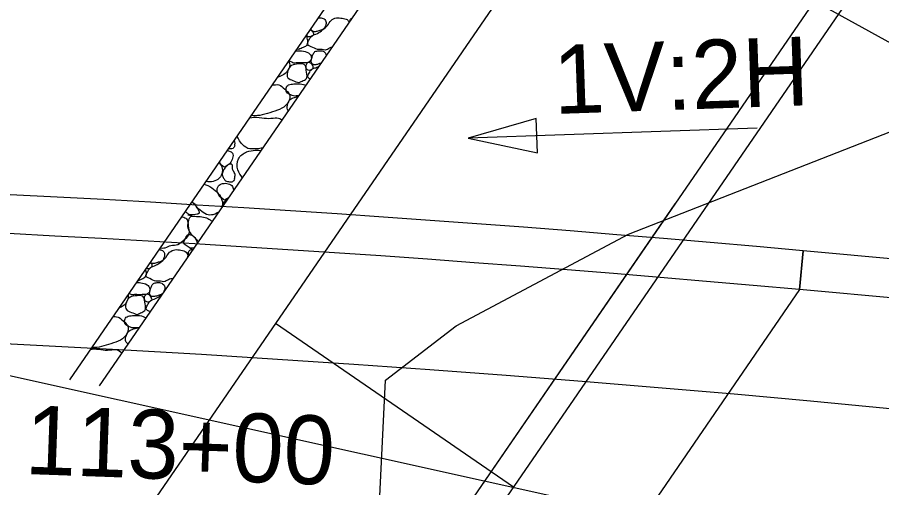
# Model space of a CAD drawing. Extents: x 1385284 to 1385995, y 1975154 to 1975620.
# Drawn here: x 1385550.34 to 1385581.75, y 1975494.43 to 1975511.52 of the extents above; entities that cross this region are included whole.
import ezdxf

# ---------------------------------------------------------------- set-up
doc = ezdxf.new("R2010")
doc.units = 0
for name, color, linetype in [('B-Super-Deck', 7, 'Continuous'), ('Default', 7, 'Continuous'), ('DTM_CONTOURS_MINOR', 7, 'Continuous'), ('R_Bridge', 7, 'Continuous'), ('R_Horz Alg Annot', 7, 'Continuous'), ('R_Proposed Const Limits', 7, 'Continuous'), ('R_Proposed Road', 7, 'Continuous')]:
    doc.layers.add(name, color=color, linetype=linetype)

msp = doc.modelspace()

# ---------------------------------------------------------------- linework, layer by layer
at = {"layer": 'B-Super-Deck'}
for p, q in [((1385588.853, 1975502.134), (1385578.894, 1975503.042)), ((1385588.724, 1975500.723), (1385578.766, 1975501.631))]:
    msp.add_line(p, q, dxfattribs=at)
at = {"layer": 'Default'}
for p, q in [((1385552.239, 1975498.351), (1385589.716, 1975552.857)), ((1385590.54, 1975552.29), (1385553.307, 1975498.139)), ((1385601.664, 1975544.642), (1385558.992, 1975482.58)), ((1385559.816, 1975482.013), (1385602.488, 1975544.075)), ((1385577.219, 1975507.501), (1385566.72, 1975507.137)), ((1385574.233, 1975504.747), (1385558.972, 1975482.551)), ((1385578.766, 1975501.631), (1385578.894, 1975503.042)), ((1385568.368, 1975494.451), (1385559.716, 1975500.4))]:
    msp.add_line(p, q, dxfattribs=at)
msp.add_lwpolyline([(1385569.196, 1975507.848), (1385566.72, 1975507.137), (1385569.24, 1975506.599)], close=True, dxfattribs=at)
for points in [[(1385561.294, 1975510.355), (1385561.222, 1975510.35), (1385561.087, 1975510.43), (1385560.827, 1975510.519), (1385560.941, 1975510.688), (1385561.02, 1975510.875), (1385561.245, 1975510.919), (1385561.445, 1975511.078), (1385561.625, 1975511.22), (1385561.72, 1975511.426), (1385561.931, 1975511.519), (1385562.146, 1975511.493), (1385562.342, 1975511.455), (1385562.378, 1975511.375), (1385562.386, 1975511.344)], [(1385561.285, 1975511.508), (1385561.348, 1975511.511), (1385561.468, 1975511.502), (1385561.574, 1975511.382), (1385561.55, 1975511.222), (1385561.49, 1975511.105), (1385561.437, 1975511.075)], [(1385562.426, 1975511.402), (1385562.436, 1975511.44), (1385562.453, 1975511.474), (1385562.49, 1975511.495)], [(1385560.985, 1975511.071), (1385561.004, 1975511.063), (1385561.064, 1975511.02), (1385561.131, 1975510.898), (1385561.043, 1975510.838), (1385561.009, 1975510.809)], [(1385561.437, 1975511.075), (1385561.389, 1975511.06), (1385561.293, 1975511.037), (1385561.159, 1975510.983), (1385561.037, 1975511.023), (1385561.005, 1975511.078), (1385561.005, 1975511.1)], [(1385560.841, 1975510.862), (1385560.847, 1975510.837), (1385560.866, 1975510.733), (1385560.906, 1975510.505), (1385560.722, 1975510.427), (1385560.619, 1975510.379), (1385560.57, 1975510.355)], [(1385561.009, 1975510.809), (1385560.972, 1975510.809), (1385560.903, 1975510.807), (1385560.858, 1975510.848), (1385560.844, 1975510.866)], [(1385560.461, 1975510.309), (1385560.545, 1975510.311), (1385560.738, 1975510.315), (1385560.988, 1975510.216), (1385561.047, 1975510.03), (1385560.951, 1975509.864), (1385560.745, 1975509.871), (1385560.585, 1975509.866), (1385560.465, 1975509.872)], [(1385560.57, 1975510.355), (1385560.548, 1975510.358), (1385560.525, 1975510.363), (1385560.503, 1975510.37)], [(1385561.359, 1975509.851), (1385561.338, 1975509.845), (1385561.267, 1975509.828), (1385561.159, 1975509.78), (1385561.032, 1975509.822), (1385561.005, 1975509.928), (1385561.035, 1975510.042), (1385561.078, 1975510.169), (1385561.139, 1975510.294), (1385561.29, 1975510.31), (1385561.461, 1975510.306), (1385561.542, 1975510.213), (1385561.559, 1975510.162), (1385561.562, 1975510.145)], [(1385561.762, 1975510.436), (1385561.749, 1975510.433), (1385561.676, 1975510.414), (1385561.539, 1975510.296), (1385561.373, 1975510.375), (1385561.294, 1975510.355)], [(1385560.465, 1975509.872), (1385560.41, 1975509.848), (1385560.31, 1975509.888), (1385560.233, 1975509.931), (1385560.211, 1975509.946)], [(1385560.199, 1975509.928), (1385560.203, 1975509.92), (1385560.267, 1975509.811), (1385560.172, 1975509.557), (1385559.973, 1975509.407), (1385559.85, 1975509.36), (1385559.795, 1975509.341)], [(1385560.57, 1975509.152), (1385560.499, 1975509.162), (1385560.354, 1975509.231), (1385560.131, 1975509.302), (1385560.134, 1975509.53), (1385560.244, 1975509.776), (1385560.46, 1975509.825), (1385560.821, 1975509.855), (1385560.824, 1975509.613), (1385560.906, 1975509.302), (1385560.722, 1975509.224), (1385560.619, 1975509.176), (1385560.57, 1975509.152)], [(1385561.009, 1975509.606), (1385560.972, 1975509.606), (1385560.887, 1975509.604), (1385560.808, 1975509.685), (1385560.816, 1975509.803), (1385560.9, 1975509.906), (1385561.027, 1975509.855), (1385561.131, 1975509.695), (1385561.043, 1975509.635), (1385561.009, 1975509.606)], [(1385560.97, 1975509.284), (1385560.936, 1975509.306), (1385560.856, 1975509.357), (1385560.941, 1975509.485), (1385561.02, 1975509.672), (1385561.196, 1975509.679), (1385561.28, 1975509.744), (1385561.292, 1975509.752)], [(1385559.606, 1975509.066), (1385559.675, 1975509.067), (1385559.852, 1975509.112), (1385560.045, 1975508.919), (1385560.298, 1975508.715), (1385560.172, 1975508.354), (1385559.883, 1975508.164), (1385559.515, 1975508.064), (1385559.144, 1975507.935), (1385558.912, 1975507.95), (1385558.841, 1975507.953)], [(1385560.465, 1975508.669), (1385560.41, 1975508.645), (1385560.265, 1975508.703), (1385560.104, 1975508.789), (1385560.093, 1975508.956), (1385560.17, 1975509.087), (1385560.389, 1975509.106), (1385560.617, 1975509.123), (1385560.785, 1975509.078), (1385560.818, 1975509.064)], [(1385560.176, 1975508.13), (1385560.129, 1975508.181), (1385560.134, 1975508.328), (1385560.244, 1975508.573), (1385560.408, 1975508.611), (1385560.512, 1975508.645), (1385560.535, 1975508.652)], [(1385560.545, 1975508.666), (1385560.518, 1975508.667), (1385560.492, 1975508.668), (1385560.465, 1975508.669)], [(1385558.788, 1975507.876), (1385558.877, 1975507.894), (1385559.135, 1975507.899), (1385559.475, 1975507.828), (1385559.795, 1975507.902), (1385559.906, 1975507.829), (1385559.946, 1975507.795)], [(1385558.838, 1975506.75), (1385558.77, 1975506.716), (1385558.547, 1975506.853), (1385558.41, 1975507.022), (1385558.34, 1975507.17), (1385558.327, 1975507.205)], [(1385558.237, 1975506.851), (1385558.227, 1975506.826), (1385558.179, 1975506.736), (1385558.09, 1975506.747), (1385558.027, 1975506.746), (1385558.011, 1975506.746)], [(1385558.217, 1975507.045), (1385558.224, 1975507.017), (1385558.267, 1975506.96), (1385558.219, 1975506.881), (1385558.237, 1975506.851)], [(1385557.972, 1975506.689), (1385557.987, 1975506.686), (1385558.067, 1975506.661), (1385558.205, 1975506.578), (1385558.154, 1975506.34), (1385558.041, 1975506.175), (1385557.937, 1975506.127), (1385557.911, 1975506.117)], [(1385558.513, 1975505.71), (1385558.457, 1975505.769), (1385558.32, 1975505.943), (1385558.303, 1975506.413), (1385558.68, 1975506.669), (1385558.99, 1975506.699), (1385559.141, 1975506.69), (1385559.184, 1975506.687)], [(1385559.244, 1975506.774), (1385559.182, 1975506.76), (1385559.047, 1975506.738), (1385558.91, 1975506.747), (1385558.838, 1975506.75)], [(1385557.677, 1975506.26), (1385557.728, 1975506.18), (1385557.81, 1975506.043), (1385557.772, 1975505.759), (1385557.587, 1975505.586), (1385557.418, 1975505.542), (1385557.334, 1975505.543)], [(1385557.911, 1975506.117), (1385557.88, 1975506.043), (1385557.74, 1975506.164), (1385557.679, 1975506.244), (1385557.673, 1975506.254)], [(1385558.237, 1975505.648), (1385558.227, 1975505.623), (1385558.179, 1975505.533), (1385558.056, 1975505.548), (1385557.878, 1975505.567), (1385557.84, 1975505.683), (1385557.766, 1975505.792), (1385557.805, 1975505.956), (1385557.899, 1975506.068), (1385557.976, 1975506.156), (1385558.056, 1975506.212), (1385558.181, 1975506.161), (1385558.138, 1975506.044), (1385558.2, 1975505.918), (1385558.282, 1975505.782), (1385558.219, 1975505.678), (1385558.237, 1975505.648)], [(1385557.334, 1975505.543), (1385557.29, 1975505.541), (1385557.246, 1975505.552), (1385557.203, 1975505.57)], [(1385557.125, 1975505.457), (1385557.213, 1975505.438), (1385557.407, 1975505.342), (1385557.662, 1975505.132), (1385557.79, 1975504.89), (1385557.804, 1975504.713), (1385557.795, 1975504.666)], [(1385557.911, 1975504.914), (1385557.88, 1975504.84), (1385557.675, 1975505.021), (1385557.573, 1975505.2), (1385557.624, 1975505.42), (1385557.788, 1975505.493), (1385558.015, 1975505.5), (1385558.176, 1975505.387), (1385558.193, 1975505.276), (1385558.187, 1975505.237)], [(1385557.779, 1975504.643), (1385557.778, 1975504.674), (1385557.815, 1975504.766), (1385557.899, 1975504.865), (1385557.958, 1975504.934), (1385557.993, 1975504.96), (1385557.999, 1975504.963)], [(1385558, 1975504.965), (1385557.994, 1975504.96), (1385557.965, 1975504.937), (1385557.937, 1975504.924), (1385557.911, 1975504.914)], [(1385556.688, 1975504.821), (1385556.726, 1975504.797), (1385556.807, 1975504.711), (1385556.87, 1975504.58), (1385557.057, 1975504.331), (1385556.307, 1975504.348), (1385556.693, 1975504.338), (1385556.685, 1975504.34)], [(1385557.334, 1975504.34), (1385557.262, 1975504.337), (1385557.08, 1975504.421), (1385556.887, 1975504.6), (1385556.759, 1975504.744), (1385556.694, 1975504.83)], [(1385556.315, 1975504.279), (1385556.318, 1975504.278), (1385556.373, 1975504.269), (1385556.54, 1975504.189), (1385556.532, 1975503.961), (1385556.619, 1975503.65), (1385556.404, 1975503.443), (1385556.182, 1975503.221), (1385555.906, 1975503.253), (1385555.698, 1975503.111), (1385555.58, 1975503.132), (1385555.53, 1975503.138)], [(1385556.651, 1975504.34), (1385556.604, 1975504.339), (1385556.53, 1975504.394), (1385556.46, 1975504.444), (1385556.44, 1975504.462)], [(1385556.91, 1975503.38), (1385556.908, 1975503.383), (1385556.826, 1975503.466), (1385556.673, 1975503.624), (1385556.514, 1975503.864), (1385556.546, 1975504.09), (1385556.617, 1975504.332), (1385556.846, 1975504.28), (1385557.116, 1975504.285), (1385557.309, 1975504.186), (1385557.402, 1975504.126), (1385557.417, 1975504.116)], [(1385557.645, 1975504.448), (1385557.627, 1975504.435), (1385557.525, 1975504.367), (1385557.418, 1975504.339), (1385557.334, 1975504.34)], [(1385556.651, 1975503.137), (1385556.604, 1975503.136), (1385556.508, 1975503.209), (1385556.345, 1975503.302), (1385556.454, 1975503.487), (1385556.502, 1975503.652), (1385556.683, 1975503.626), (1385556.802, 1975503.521), (1385556.846, 1975503.404), (1385556.871, 1975503.335), (1385556.874, 1975503.327)], [(1385555.425, 1975501.934), (1385555.353, 1975501.929), (1385555.218, 1975502.009), (1385554.958, 1975502.099), (1385555.072, 1975502.267), (1385555.151, 1975502.454), (1385555.376, 1975502.499), (1385555.576, 1975502.657), (1385555.755, 1975502.799), (1385555.85, 1975503.005), (1385556.062, 1975503.098), (1385556.277, 1975503.072), (1385556.512, 1975503.006), (1385556.526, 1975502.894), (1385556.533, 1975502.831)], [(1385555.494, 1975503.085), (1385555.531, 1975503.081), (1385555.615, 1975503.062), (1385555.705, 1975502.961), (1385555.681, 1975502.801), (1385555.62, 1975502.684), (1385555.567, 1975502.654)], [(1385556.533, 1975502.831), (1385556.534, 1975502.856), (1385556.551, 1975502.938), (1385556.589, 1975503.086), (1385556.681, 1975503.093), (1385556.712, 1975503.091)], [(1385556.749, 1975503.145), (1385556.7, 1975503.141), (1385556.514, 1975503.14), (1385556.693, 1975503.135), (1385556.685, 1975503.137)], [(1385555.14, 1975502.388), (1385555.102, 1975502.388), (1385555.064, 1975502.387), (1385555.026, 1975502.403), (1385555.025, 1975502.404)], [(1385555.171, 1975502.616), (1385555.218, 1975502.575), (1385555.261, 1975502.477), (1385555.173, 1975502.417), (1385555.14, 1975502.388)], [(1385555.567, 1975502.654), (1385555.52, 1975502.639), (1385555.424, 1975502.616), (1385555.29, 1975502.563), (1385555.206, 1975502.585), (1385555.171, 1975502.616)], [(1385554.993, 1975502.356), (1385555.017, 1975502.27), (1385555.034, 1975502.083), (1385554.853, 1975502.007), (1385554.751, 1975501.959), (1385554.703, 1975501.935)], [(1385554.671, 1975501.889), (1385554.729, 1975501.888), (1385554.891, 1975501.884), (1385555.118, 1975501.795), (1385555.178, 1975501.609), (1385555.082, 1975501.443), (1385554.876, 1975501.45), (1385554.716, 1975501.445), (1385554.596, 1975501.451)], [(1385555.567, 1975501.451), (1385555.52, 1975501.436), (1385555.424, 1975501.413), (1385555.289, 1975501.359), (1385555.163, 1975501.401), (1385555.135, 1975501.508), (1385555.166, 1975501.621), (1385555.209, 1975501.748), (1385555.27, 1975501.873), (1385555.42, 1975501.889), (1385555.592, 1975501.885), (1385555.705, 1975501.758), (1385555.698, 1975501.639), (1385555.667, 1975501.574), (1385555.662, 1975501.564)], [(1385555.982, 1975502.029), (1385555.939, 1975502.024), (1385555.834, 1975502.009), (1385555.669, 1975501.875), (1385555.504, 1975501.954), (1385555.425, 1975501.934)], [(1385554.596, 1975501.451), (1385554.541, 1975501.427), (1385554.466, 1975501.458), (1385554.403, 1975501.49), (1385554.398, 1975501.492)], [(1385555.14, 1975501.185), (1385555.102, 1975501.185), (1385555.018, 1975501.183), (1385554.938, 1975501.265), (1385554.946, 1975501.383), (1385555.031, 1975501.485), (1385555.158, 1975501.435), (1385555.261, 1975501.274), (1385555.173, 1975501.214), (1385555.14, 1975501.185)], [(1385555.157, 1975500.83), (1385555.1, 1975500.86), (1385554.971, 1975500.915), (1385555.072, 1975501.064), (1385555.151, 1975501.251), (1385555.376, 1975501.296), (1385555.527, 1975501.413), (1385555.6, 1975501.481), (1385555.615, 1975501.497)], [(1385555.602, 1975501.477), (1385555.592, 1975501.467), (1385555.58, 1975501.458), (1385555.567, 1975501.451)], [(1385554.359, 1975501.434), (1385554.38, 1975501.333), (1385554.289, 1975501.125), (1385554.139, 1975501.002), (1385554.052, 1975500.967), (1385554.033, 1975500.96)], [(1385554.701, 1975500.731), (1385554.629, 1975500.741), (1385554.485, 1975500.811), (1385554.261, 1975500.881), (1385554.264, 1975501.109), (1385554.374, 1975501.355), (1385554.59, 1975501.404), (1385554.952, 1975501.434), (1385554.955, 1975501.192), (1385555.037, 1975500.881), (1385554.852, 1975500.804), (1385554.75, 1975500.756), (1385554.701, 1975500.731)], [(1385553.818, 1975500.648), (1385553.86, 1975500.65), (1385554.002, 1975500.669), (1385554.176, 1975500.498), (1385554.428, 1975500.294), (1385554.303, 1975499.934), (1385554.014, 1975499.743), (1385553.646, 1975499.643), (1385553.301, 1975499.523), (1385553.094, 1975499.527), (1385553.048, 1975499.528)], [(1385554.596, 1975500.248), (1385554.541, 1975500.224), (1385554.396, 1975500.282), (1385554.234, 1975500.368), (1385554.224, 1975500.535), (1385554.301, 1975500.667), (1385554.52, 1975500.685), (1385554.775, 1975500.707), (1385554.956, 1975500.644), (1385555.007, 1975500.612)], [(1385554.356, 1975499.665), (1385554.339, 1975499.677), (1385554.26, 1975499.736), (1385554.264, 1975499.906), (1385554.374, 1975500.152), (1385554.559, 1975500.195), (1385554.703, 1975500.245), (1385554.756, 1975500.247)], [(1385554.755, 1975500.245), (1385554.702, 1975500.245), (1385554.649, 1975500.245), (1385554.596, 1975500.248)], [(1385553.008, 1975499.469), (1385553.067, 1975499.477), (1385553.295, 1975499.475), (1385553.606, 1975499.407), (1385553.953, 1975499.492), (1385554.069, 1975499.382), (1385554.125, 1975499.33)]]:
    msp.add_open_spline(points, degree=3, dxfattribs=at)
at = {"layer": 'DTM_CONTOURS_MINOR'}
msp.add_lwpolyline([(1385562.866, 1975481.018), (1385563.716, 1975498.339), (1385566.287, 1975500.31), (1385572.546, 1975503.642), (1385585.482, 1975508.711), (1385572.018, 1975516.132), (1385577.884, 1975524.056), (1385581.986, 1975529.59), (1385586.864, 1975537.76), (1385589.378, 1975541.298), (1385592.421, 1975550.843), (1385595.925, 1975556.919), (1385603.651, 1975570.298), (1385603.747, 1975570.566), (1385603.842, 1975570.633), (1385603.931, 1975570.594), (1385610.734, 1975574.084), (1385616.057, 1975580.707), (1385617.625, 1975582.015), (1385623.884, 1975585.062), (1385632.559, 1975588.36), (1385643.399, 1975583.605), (1385645.132, 1975583.412)], dxfattribs=at)
at = {"layer": 'R_Bridge'}
for p, q in [((1385578.894, 1975503.042), (1385578.766, 1975501.631)), ((1385578.766, 1975501.631), (1385559.137, 1975473.083))]:
    msp.add_line(p, q, dxfattribs=at)
for radius in [710.911, 709.494]:
    msp.add_arc((1385514.357, 1974795.066), radius, 84.79144, 93.554346, dxfattribs=at)
at = {"layer": 'R_Horz Alg Annot'}
msp.add_line((1385315.54, 1975550.51), (1385664.693, 1975473.094), dxfattribs=at)
at = {"layer": 'R_Proposed Const Limits'}
msp.add_line((1385593.836, 1975550.024), (1385551.164, 1975487.962), dxfattribs=at)
at = {"layer": 'R_Proposed Road'}
msp.add_arc((1385514.357, 1974795.066), 705.494, 77.498258, 106.368381, dxfattribs=at)

# ---------------------------------------------------------------- texts
at = {"layer": 'Default'}
for s, rotation, p in [('1V:2H', 1.9864, (1385569.855, 1975508.01)), ('113+00', 357.9446, (1385550.59, 1975494.934))]:
    msp.add_text(s, height=2.5, rotation=rotation, dxfattribs=at).set_placement(p)

doc.saveas('drawing.dxf')
